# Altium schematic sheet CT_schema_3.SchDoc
size 287 x 169 mm
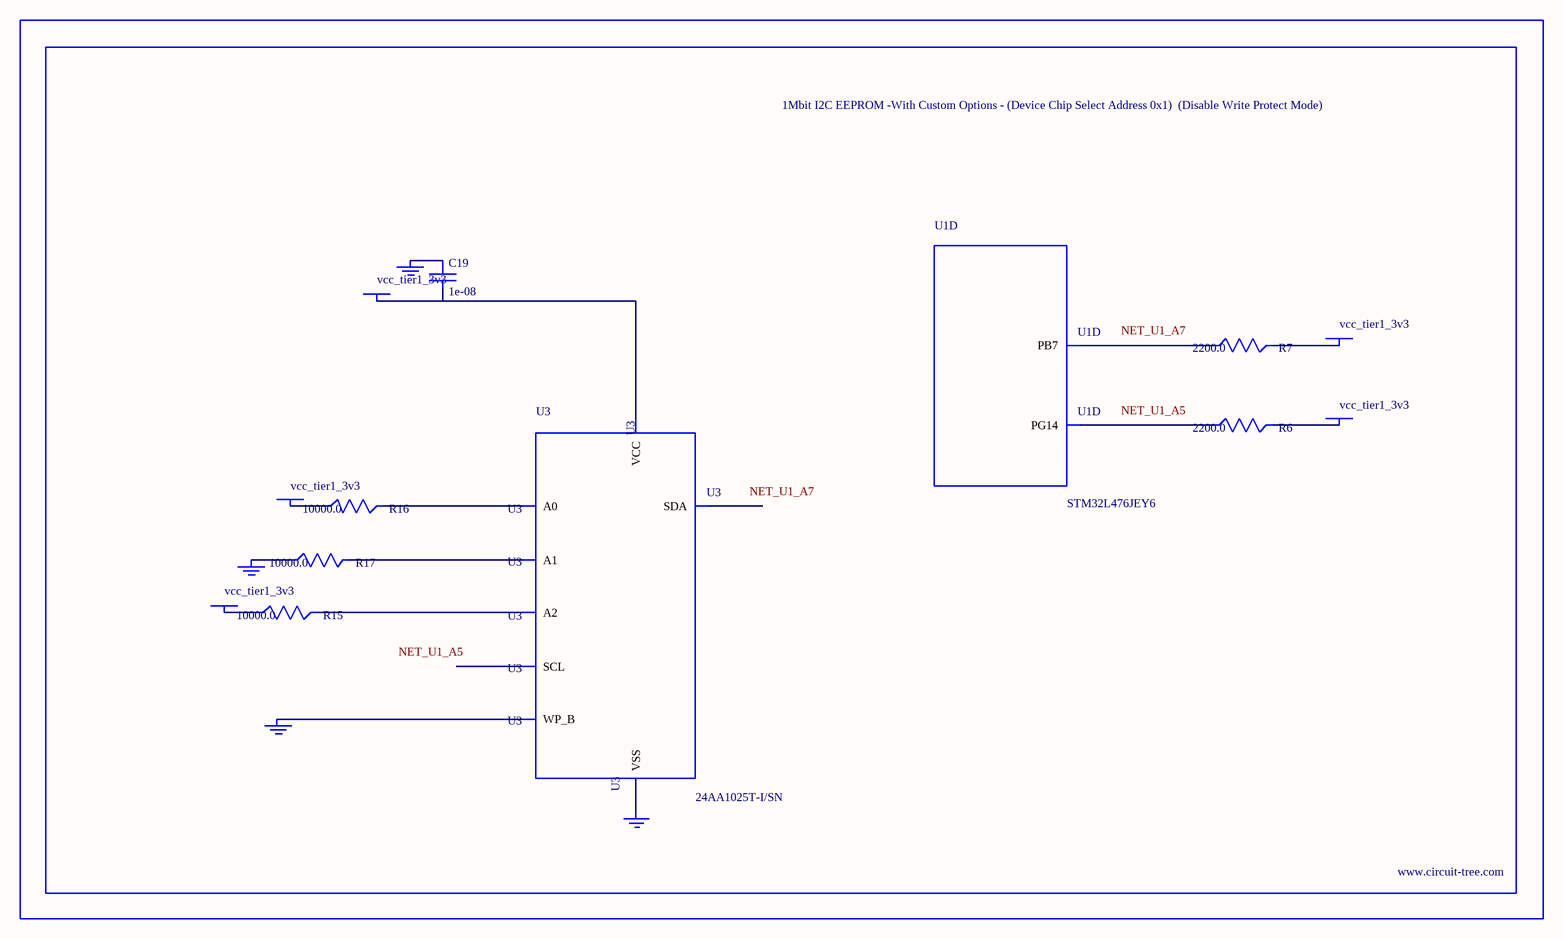
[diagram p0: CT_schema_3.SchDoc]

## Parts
BORDER2  (no value)
C19  1e-08  [C0402]
GND_INSTANCE_2_0  (no value)
GND_INSTANCE_2_1  (no value)
GND_INSTANCE_2_2  (no value)
GND_INSTANCE_2_3  (no value)
POWER_INSTANCE_2_0  vcc_tier1_3v3
POWER_INSTANCE_2_1  vcc_tier1_3v3
POWER_INSTANCE_2_2  vcc_tier1_3v3
POWER_INSTANCE_2_3  vcc_tier1_3v3
POWER_INSTANCE_2_4  vcc_tier1_3v3
R6  2200.0  [R0603]
R7  2200.0  [R0603]
R15  10000.0  [R0603]
R16  10000.0  [R0603]
R17  10000.0  [R0603]
U1  STM32L476JEY6  [WLCSP72]  (part D of 6)
U3  24AA1025T-I/SN  [SOIC-8]

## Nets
NetC19_1: C19.1 GND_INSTANCE_2_2.0(GND)
NetC19_2: C19.2 POWER_INSTANCE_2_2.0(PWR) U3.8(VCC)
NetGND_INSTANCE_2_0_0: GND_INSTANCE_2_0.0(GND) R17.1
NetGND_INSTANCE_2_1_0: GND_INSTANCE_2_1.0(GND) U3.7(WP_B)
NetGND_INSTANCE_2_3_0: GND_INSTANCE_2_3.0(GND) U3.4(VSS)
NetPOWER_INSTANCE_2_0_0: POWER_INSTANCE_2_0.0(PWR) R16.1
NetPOWER_INSTANCE_2_1_0: POWER_INSTANCE_2_1.0(PWR) R15.1
NetPOWER_INSTANCE_2_3_0: POWER_INSTANCE_2_3.0(PWR) R7.2
NetPOWER_INSTANCE_2_4_0: POWER_INSTANCE_2_4.0(PWR) R6.2
NetR6_1: R6.1 U1.A5(PG14)
NetR7_1: R7.1 U1.A7(PB7)
NetR15_2: R15.2 U3.3(A2)
NetR16_2: R16.2 U3.1(A0)
NetR17_2: R17.2 U3.2(A1)

Not connected (* = marked no-connect by the designer): U3 5(SDA) 6(SCL)

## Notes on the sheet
- Labels drawn without touching a wire or pin: NET_U1_A5, NET_U1_A7

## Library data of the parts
BORDER2 = BORDER_PAGE2
C19 = C0402C103K3RAC
GND_INSTANCE_2_0-GND_INSTANCE_2_3 = GND
POWER_INSTANCE_2_0-POWER_INSTANCE_2_4 = PWR
R6 R7 = RC0603JR-072K2L
R15-R17 = RC0603JR-0710KL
